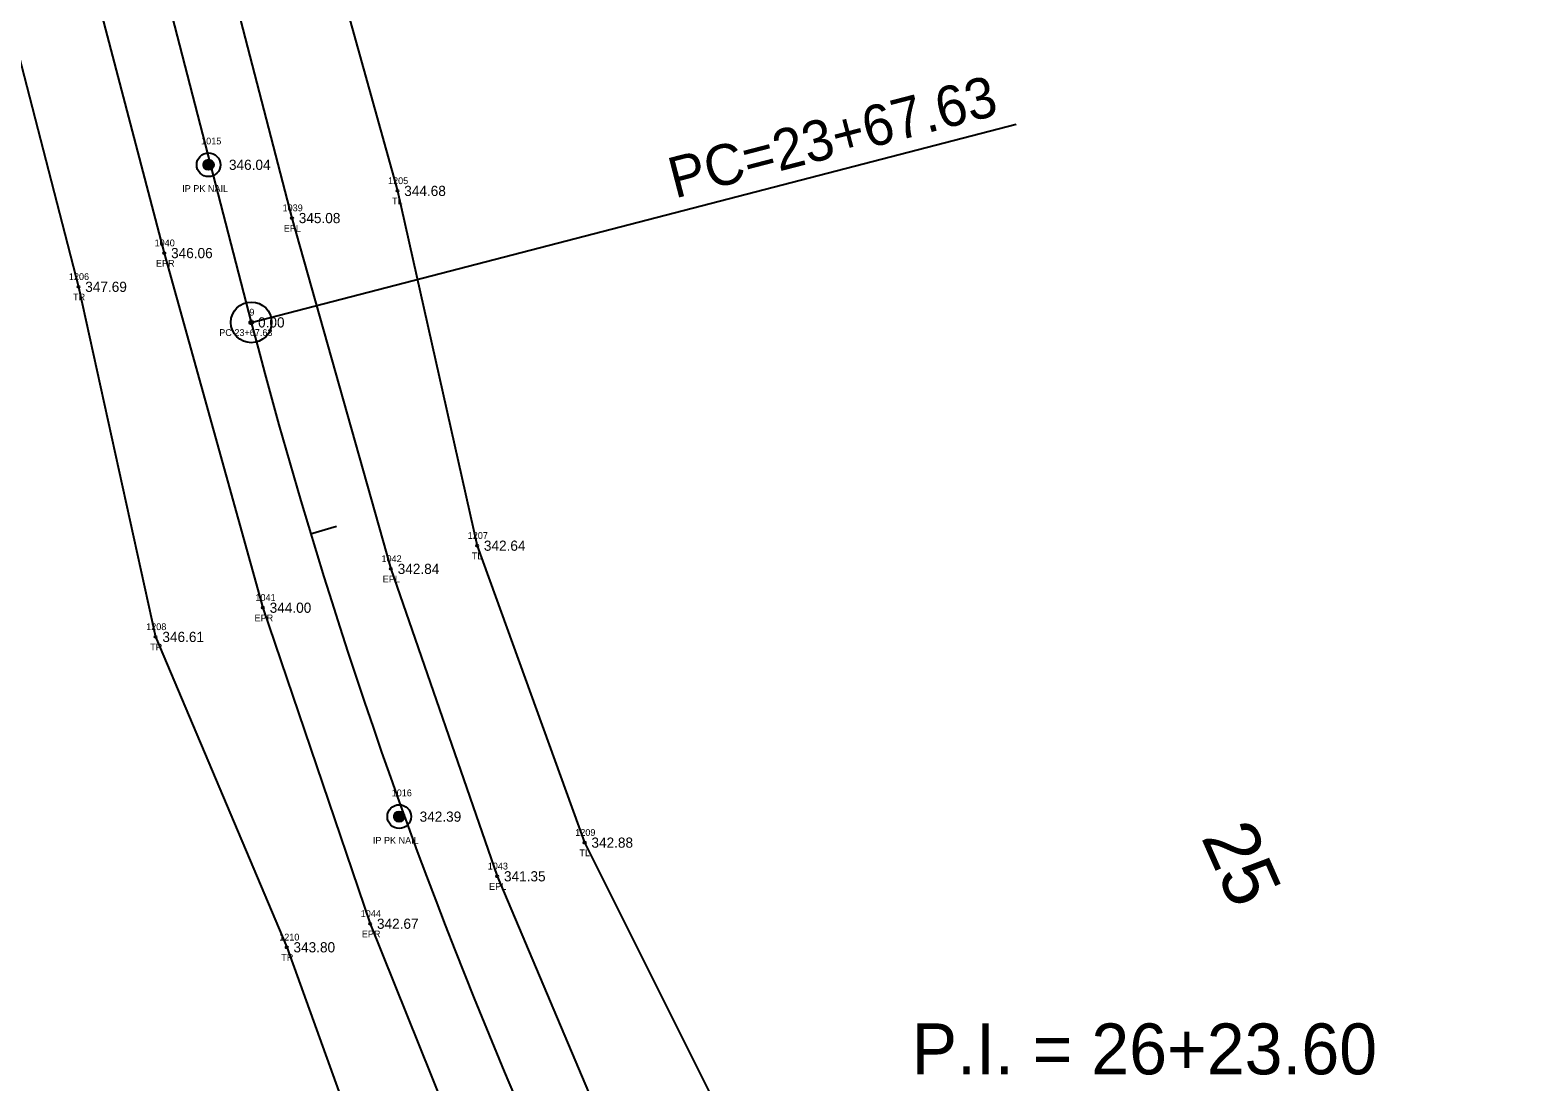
# Model space of a CAD drawing. Extents: x 2006517 to 2008868, y 1001613 to 1004633.
# Drawn here: x 2007268.1 to 2007490.3, y 1003493.9 to 1003648.8 of the extents above; entities that cross this region are included whole.
import ezdxf

# ---------------------------------------------------------------- set-up
doc = ezdxf.new("R2010")
doc.units = 0
for name, color, linetype in [('RD_EX_DV_Prop_txCode', 7, 'Continuous'), ('RD_EX_DV_PropPin', 7, 'Continuous'), ('RD_EX_Road', 7, 'Continuous'), ('RD_EX_Road_txCode', 7, 'Continuous'), ('RD_EX_TX_DV_Prop_ELEV', 7, 'Continuous'), ('RD_EX_TX_Road_ELEV', 7, 'Continuous'), ('RD_EX_TX_VEG_ELEV', 7, 'Continuous'), ('RD_EX_VEG', 7, 'Continuous'), ('RD_EX_VEG_txCode', 7, 'Continuous'), ('RD_HC_Cl', 7, 'Continuous'), ('RD_HC_Data', 7, 'Continuous'), ('RD_HC_Data_Tic', 7, 'Continuous'), ('RD_HC_Survey_ELEV', 7, 'Continuous'), ('RD_HC_TX_Sta50', 7, 'Continuous'), ('RD_HC_txCode', 7, 'Continuous'), ('RD_SMD_Locator', 7, 'Continuous')]:
    doc.layers.add(name, color=color, linetype=linetype)

msp = doc.modelspace()

# ---------------------------------------------------------------- linework, layer by layer
at = {"layer": 'RD_EX_DV_PropPin'}
for p, q in [((2007293.9, 1003628.43), (2007293.9, 1003629.6)), ((2007293.94, 1003628.4), (2007293.94, 1003629.62)), ((2007293.97, 1003628.38), (2007293.97, 1003629.65)), ((2007294.01, 1003628.36), (2007294.01, 1003629.67)), ((2007294.04, 1003628.34), (2007294.04, 1003629.69)), ((2007294.08, 1003628.32), (2007294.08, 1003629.71)), ((2007294.11, 1003628.31), (2007294.11, 1003629.72)), ((2007294.15, 1003628.29), (2007294.15, 1003629.73)), ((2007294.18, 1003628.28), (2007294.18, 1003629.75)), ((2007294.22, 1003628.27), (2007294.22, 1003629.76)), ((2007294.25, 1003628.27), (2007294.25, 1003629.76)), ((2007294.29, 1003628.26), (2007294.29, 1003629.77)), ((2007294.32, 1003628.26), (2007294.32, 1003629.77)), ((2007294.36, 1003628.25), (2007294.36, 1003629.77)), ((2007294.39, 1003628.25), (2007294.39, 1003629.78)), ((2007294.43, 1003628.25), (2007294.43, 1003629.77)), ((2007294.46, 1003628.26), (2007294.46, 1003629.77)), ((2007294.5, 1003628.26), (2007294.5, 1003629.77)), ((2007294.53, 1003628.27), (2007294.53, 1003629.76)), ((2007294.57, 1003628.27), (2007294.57, 1003629.76)), ((2007294.6, 1003628.28), (2007294.6, 1003629.75)), ((2007294.64, 1003628.29), (2007294.64, 1003629.73)), ((2007294.67, 1003628.31), (2007294.67, 1003629.72)), ((2007294.71, 1003628.32), (2007294.71, 1003629.71)), ((2007294.74, 1003628.34), (2007294.74, 1003629.69)), ((2007294.78, 1003628.36), (2007294.78, 1003629.67)), ((2007294.81, 1003628.38), (2007294.81, 1003629.65)), ((2007294.85, 1003628.4), (2007294.85, 1003629.62)), ((2007294.88, 1003628.43), (2007294.88, 1003629.6)), ((2007293.66, 1003628.82), (2007293.66, 1003629.21)), ((2007293.69, 1003628.72), (2007293.69, 1003629.31)), ((2007293.73, 1003628.64), (2007293.73, 1003629.38)), ((2007293.76, 1003628.59), (2007293.76, 1003629.44)), ((2007293.8, 1003628.54), (2007293.8, 1003629.49)), ((2007293.83, 1003628.5), (2007293.83, 1003629.53)), ((2007293.87, 1003628.46), (2007293.87, 1003629.57)), ((2007294.92, 1003628.46), (2007294.92, 1003629.57)), ((2007294.95, 1003628.5), (2007294.95, 1003629.53)), ((2007294.99, 1003628.54), (2007294.99, 1003629.49)), ((2007295.02, 1003628.59), (2007295.02, 1003629.44)), ((2007295.06, 1003628.64), (2007295.06, 1003629.38)), ((2007295.09, 1003628.72), (2007295.09, 1003629.31)), ((2007295.13, 1003628.82), (2007295.13, 1003629.21)), ((2007321.76, 1003532.77), (2007321.76, 1003533.17)), ((2007321.79, 1003532.67), (2007321.79, 1003533.27)), ((2007321.83, 1003532.6), (2007321.83, 1003533.34)), ((2007321.86, 1003532.54), (2007321.86, 1003533.4)), ((2007321.9, 1003532.5), (2007321.9, 1003533.44)), ((2007321.93, 1003532.45), (2007321.93, 1003533.48)), ((2007321.97, 1003532.42), (2007321.97, 1003533.52)), ((2007322, 1003532.39), (2007322, 1003533.55)), ((2007322.04, 1003532.36), (2007322.04, 1003533.58)), ((2007322.07, 1003532.33), (2007322.07, 1003533.6)), ((2007322.11, 1003532.31), (2007322.11, 1003533.63)), ((2007322.14, 1003532.29), (2007322.14, 1003533.64)), ((2007322.18, 1003532.28), (2007322.18, 1003533.66)), ((2007322.21, 1003532.26), (2007322.21, 1003533.68)), ((2007322.25, 1003532.25), (2007322.25, 1003533.69)), ((2007322.28, 1003532.24), (2007322.28, 1003533.7)), ((2007322.32, 1003532.23), (2007322.32, 1003533.71)), ((2007322.35, 1003532.22), (2007322.35, 1003533.72)), ((2007322.39, 1003532.22), (2007322.39, 1003533.72)), ((2007322.42, 1003532.21), (2007322.42, 1003533.73)), ((2007322.46, 1003532.21), (2007322.46, 1003533.73)), ((2007322.49, 1003532.21), (2007322.49, 1003533.73)), ((2007322.53, 1003532.21), (2007322.53, 1003533.73)), ((2007322.56, 1003532.21), (2007322.56, 1003533.73)), ((2007322.6, 1003532.22), (2007322.6, 1003533.72)), ((2007322.63, 1003532.22), (2007322.63, 1003533.72)), ((2007322.67, 1003532.23), (2007322.67, 1003533.71)), ((2007322.7, 1003532.24), (2007322.7, 1003533.7)), ((2007322.74, 1003532.25), (2007322.74, 1003533.69)), ((2007322.77, 1003532.26), (2007322.77, 1003533.68)), ((2007322.81, 1003532.28), (2007322.81, 1003533.66)), ((2007322.84, 1003532.29), (2007322.84, 1003533.64)), ((2007322.88, 1003532.31), (2007322.88, 1003533.63)), ((2007322.91, 1003532.33), (2007322.91, 1003533.6)), ((2007322.95, 1003532.36), (2007322.95, 1003533.58)), ((2007322.98, 1003532.39), (2007322.98, 1003533.55)), ((2007323.02, 1003532.42), (2007323.02, 1003533.52)), ((2007323.05, 1003532.45), (2007323.05, 1003533.48)), ((2007323.09, 1003532.5), (2007323.09, 1003533.44)), ((2007323.12, 1003532.54), (2007323.12, 1003533.4)), ((2007323.16, 1003532.6), (2007323.16, 1003533.34)), ((2007323.19, 1003532.67), (2007323.19, 1003533.27)), ((2007323.23, 1003532.77), (2007323.23, 1003533.17))]:
    msp.add_line(p, q, dxfattribs=at)
for centre, radius in [((2007294.39, 1003629.01), 1.75), ((2007294.39, 1003629.01), 0.761), ((2007322.49, 1003532.97), 1.75), ((2007322.49, 1003532.97), 0.761)]:
    msp.add_circle(centre, radius, dxfattribs=at)
at = {"layer": 'RD_EX_Road'}
for points in [[(2007106.91, 1004392.51), (2007131.76, 1004296.89), (2007157.25, 1004199.89), (2007181.73, 1004104.01), (2007207.15, 1004006.25), (2007232.28, 1003909.68), (2007245.22, 1003859.08), (2007256.72, 1003814.23), (2007281.54, 1003717.98), (2007306.68, 1003621.16), (2007321.26, 1003569.47), (2007336.92, 1003524.18), (2007356.72, 1003477.39), (2007378.16, 1003434.29), (2007403.27, 1003391.08), (2007429.97, 1003350.71), (2007461.24, 1003310.36), (2007493.28, 1003274.3), (2007528.72, 1003239.05), (2007564.79, 1003204.88), (2007704.21, 1003083.21), (2007697.4, 1003075.08)], [(2007086.98, 1004389.35), (2007112.54, 1004291.29), (2007137.93, 1004194.16), (2007162.5, 1004098.34), (2007187.86, 1004000.45), (2007213, 1003903.71), (2007225.92, 1003855.13), (2007237.94, 1003808.26), (2007262.59, 1003712.12), (2007287.86, 1003616), (2007302.39, 1003563.75), (2007318.2, 1003517.19), (2007334.44, 1003476.78), (2007338.05, 1003468.98), (2007341.25, 1003461.96), (2007359.99, 1003424.53), (2007383.83, 1003381.83), (2007412.14, 1003338.08), (2007443.3, 1003296.86), (2007477.49, 1003258.92), (2007512.95, 1003223.51), (2007550.46, 1003188.01), (2007690.1, 1003066.42), (2007697.4, 1003075.08)]]:
    msp.add_lwpolyline(points, dxfattribs=at)
at = {"layer": 'RD_EX_VEG'}
for points in [[(2007147.61, 1004399.6), (2007180.32, 1004302.7), (2007203.48, 1004211.02), (2007229.33, 1004116.12), (2007255.87, 1004020.69), (2007274.38, 1003918.82), (2007311.82, 1003829.26), (2007295.76, 1003720.22), (2007322.22, 1003625.16), (2007333.96, 1003572.89), (2007349.81, 1003529.14), (2007372.14, 1003484.48), (2007389.48, 1003440.89), (2007415.49, 1003398.14), (2007443.34, 1003359.22), (2007473.93, 1003322.69), (2007503.07, 1003282.99)], [(2007072.69, 1004383.47), (2007099, 1004287.92), (2007126.08, 1004191.47), (2007151.91, 1004096.57), (2007177.65, 1003996.18), (2007202.96, 1003899.08), (2007225.61, 1003813.8), (2007249.14, 1003712.01), (2007275.21, 1003611.03), (2007286.58, 1003559.45), (2007305.9, 1003513.72), (2007341.13, 1003416), (2007368.23, 1003371.03), (2007395.89, 1003327.12), (2007429.8, 1003285.17)]]:
    msp.add_lwpolyline(points, dxfattribs=at)
at = {"layer": 'RD_HC_Cl'}
msp.add_line((2007095.5, 1004397.25), (2007300.68, 1003605.79), dxfattribs=at)
msp.add_arc((2008085.61, 1003809.27), 810.87, 194.53337, 229.57273, dxfattribs=at)
at = {"layer": 'RD_HC_Data'}
msp.add_line((2007300.68, 1003605.79), (2007413.4, 1003635.01), dxfattribs=at)
for radius in [3, 0.282]:
    msp.add_circle((2007300.68, 1003605.79), radius, dxfattribs=at)
at = {"layer": 'RD_HC_Data_Tic'}
msp.add_line((2007309.43, 1003574.62), (2007313.25, 1003575.78), dxfattribs=at)
at = {"layer": 'RD_SMD_Locator'}
for centre in [(2007294.39, 1003629.01), (2007322.22, 1003625.16), (2007306.68, 1003621.16), (2007287.86, 1003616), (2007275.21, 1003611.03), (2007300.68, 1003605.79), (2007333.96, 1003572.89), (2007321.26, 1003569.47), (2007302.39, 1003563.75), (2007286.58, 1003559.45), (2007322.49, 1003532.97), (2007349.81, 1003529.14), (2007336.92, 1003524.18), (2007318.2, 1003517.19), (2007305.9, 1003513.72)]:
    msp.add_circle(centre, 0.15, dxfattribs=at)

# ---------------------------------------------------------------- texts
at = {"layer": 'RD_EX_DV_Prop_txCode'}
for s, p in [('1015', (2007293.29, 1003632.01)), ('IP PK NAIL', (2007290.5, 1003625.01)), ('1016', (2007321.37, 1003535.97)), ('IP PK NAIL', (2007318.6, 1003528.97))]:
    msp.add_text(s, height=1, dxfattribs=at).set_placement(p)
at = {"layer": 'RD_EX_Road_txCode'}
for s, p in [('1039', (2007305.29, 1003622.16)), ('EPL', (2007305.47, 1003619.16)), ('1040', (2007286.43, 1003617)), ('EPR', (2007286.63, 1003614)), ('1042', (2007319.87, 1003570.47)), ('EPL', (2007320.05, 1003567.47)), ('1041', (2007301.29, 1003564.75)), ('EPR', (2007301.16, 1003561.75)), ('1043', (2007335.53, 1003525.18)), ('EPL', (2007335.72, 1003522.18)), ('1044', (2007316.81, 1003518.19)), ('EPR', (2007316.97, 1003515.19))]:
    msp.add_text(s, height=1, dxfattribs=at).set_placement(p)
at = {"layer": 'RD_EX_TX_DV_Prop_ELEV'}
for s, p in [('346.04', (2007297.39, 1003628.26)), ('342.39', (2007325.49, 1003532.22))]:
    msp.add_text(s, height=1.5, dxfattribs=at).set_placement(p)
at = {"layer": 'RD_EX_TX_Road_ELEV'}
for s, p in [('345.08', (2007307.68, 1003620.41)), ('346.06', (2007288.86, 1003615.25)), ('342.84', (2007322.26, 1003568.72)), ('344.00', (2007303.39, 1003563)), ('341.35', (2007337.92, 1003523.43)), ('342.67', (2007319.2, 1003516.44))]:
    msp.add_text(s, height=1.5, dxfattribs=at).set_placement(p)
at = {"layer": 'RD_EX_TX_VEG_ELEV'}
for s, p in [('344.68', (2007323.22, 1003624.41)), ('347.69', (2007276.21, 1003610.28)), ('342.64', (2007334.96, 1003572.14)), ('346.61', (2007287.58, 1003558.7)), ('342.88', (2007350.81, 1003528.39)), ('343.80', (2007306.9, 1003512.97))]:
    msp.add_text(s, height=1.5, dxfattribs=at).set_placement(p)
at = {"layer": 'RD_EX_VEG_txCode'}
for s, p in [('1205', (2007320.83, 1003626.16)), ('TL', (2007321.44, 1003623.16)), ('1206', (2007273.8, 1003612.03)), ('TR', (2007274.42, 1003609.03)), ('1207', (2007332.58, 1003573.89)), ('TL', (2007333.19, 1003570.89)), ('1208', (2007285.19, 1003560.45)), ('TR', (2007285.78, 1003557.45)), ('1209', (2007348.42, 1003530.14)), ('TL', (2007349.04, 1003527.14)), ('1210', (2007304.79, 1003514.72)), ('TR', (2007305.1, 1003511.72))]:
    msp.add_text(s, height=1, dxfattribs=at).set_placement(p)
at = {"layer": 'RD_HC_Data'}
msp.add_text('PC=23+67.63', height=6, rotation=14.5334, dxfattribs=at).set_placement((2007363.1, 1003624.03))
msp.add_text('P.I. = 26+23.60', height=7.5, dxfattribs=at).set_placement((2007398, 1003495))
at = {"layer": 'RD_HC_Survey_ELEV'}
msp.add_text('0.00', height=1.5, dxfattribs=at).set_placement((2007301.68, 1003605.04))
at = {"layer": 'RD_HC_TX_Sta50'}
msp.add_text('25', height=8, rotation=293.8865, dxfattribs=at).set_placement((2007440.6, 1003529.93))
at = {"layer": 'RD_HC_txCode'}
for s, p in [('9', (2007300.4, 1003606.79)), ('PC 23+67.63', (2007295.96, 1003603.79))]:
    msp.add_text(s, height=1, dxfattribs=at).set_placement(p)

doc.saveas('drawing.dxf')
